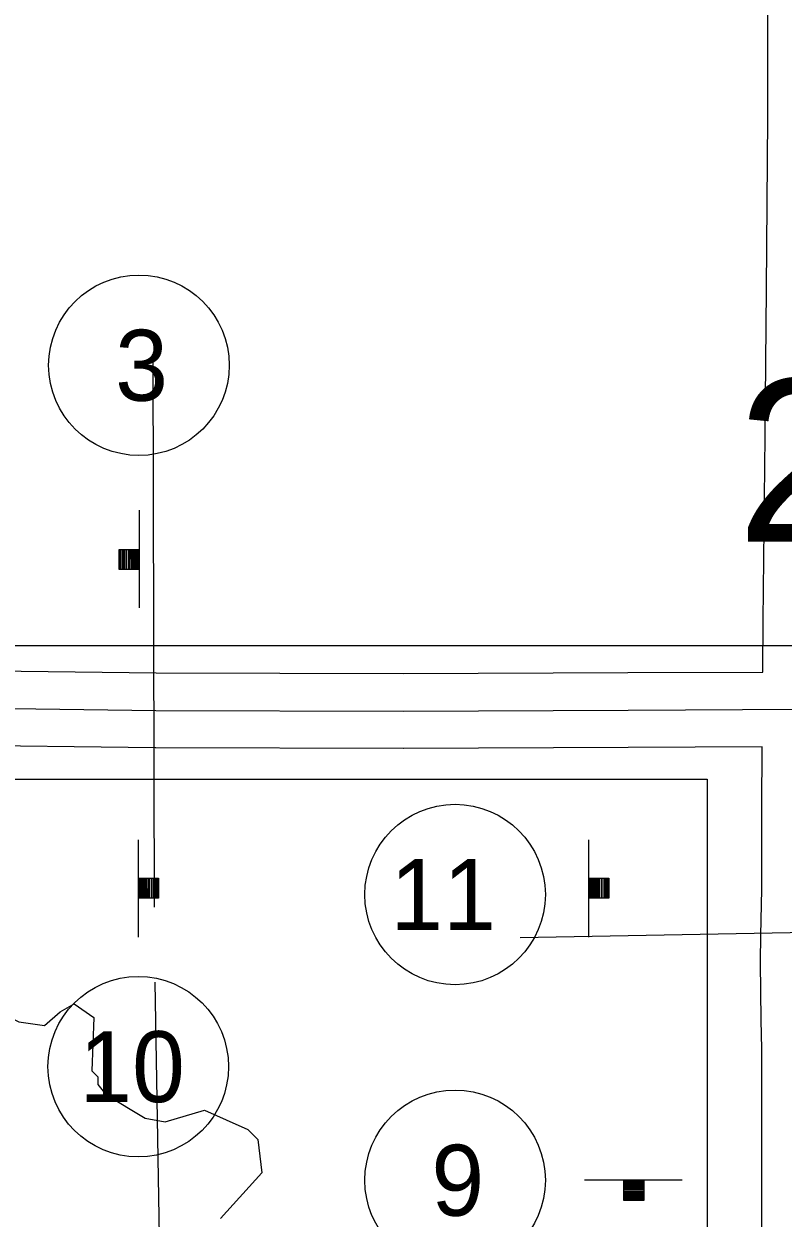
# Model space of a CAD drawing. Extents: x -2251611 to -2054719, y -2227156 to -2099355.
# Drawn here: x -2130609 to -2127401, y -2126976 to -2121927 of the extents above; entities that cross this region are included whole.
import ezdxf

# ---------------------------------------------------------------- set-up
doc = ezdxf.new("R2010")
doc.units = 0
for name, color, linetype in [('Default', 7, 'Continuous'), ('dsnTextFinalPlan', 7, 'Continuous'), ('dsnTextNote', 7, 'Continuous'), ('tdCoHydroRiver', 7, 'Continuous'), ('tdCoSecRteBand', 7, 'Continuous'), ('tdCoSectLinePart', 7, 'Continuous'), ('tdCoSectNmbr', 7, 'Continuous'), ('tdCoSurfAsphalt', 7, 'Continuous')]:
    doc.layers.add(name, color=color, linetype=linetype)

msp = doc.modelspace()

# ---------------------------------------------------------------- linework, layer by layer
at = {"layer": 'Default'}
for p, q in [((-2127105.2, -2124556.4), (-2138233.4, -2124556.4)), ((-2137523.9, -2125120.3), (-2127721.9, -2125120.3)), ((-2127721.9, -2125120.3), (-2127721.9, -2135863.1))]:
    msp.add_line(p, q, dxfattribs=at)
at = {"layer": 'dsnTextFinalPlan'}
for p, q in [((-2130120.8, -2124395.8), (-2130120.8, -2123983.3)), ((-2130200.7, -2124232.9), (-2130200.7, -2124149)), ((-2130195.9, -2124149), (-2130195.9, -2124232.9)), ((-2130192.5, -2124232.9), (-2130192.5, -2124149)), ((-2130187.7, -2124149), (-2130187.7, -2124232.9)), ((-2130184.4, -2124232.9), (-2130184.6, -2124149)), ((-2130178.2, -2124149), (-2130177.9, -2124232.9)), ((-2130174.8, -2124232.9), (-2130174.8, -2124149)), ((-2130168.3, -2124149), (-2130168.3, -2124232.9)), ((-2130162.7, -2124232.9), (-2130162.7, -2124149)), ((-2130157.9, -2124149), (-2130157.6, -2124232.9)), ((-2130154.5, -2124232.9), (-2130154.5, -2124149)), ((-2130150.6, -2124149), (-2130150.6, -2124232.9)), ((-2130145.5, -2124232.9), (-2130145.5, -2124149)), ((-2130142.4, -2124149), (-2130142.4, -2124232.9)), ((-2130139.1, -2124232.9), (-2130139.1, -2124149)), ((-2130135.1, -2124149), (-2130135.1, -2124232.9)), ((-2130131.2, -2124232.9), (-2130131.2, -2124149)), ((-2130127, -2124149), (-2130127, -2124232.9)), ((-2130126, -2125376.2), (-2130126, -2125788.7)), ((-2128222.6, -2125376.2), (-2128222.6, -2125788.7)), ((-2130119.8, -2125623), (-2130119.8, -2125539.1)), ((-2130115.5, -2125539.1), (-2130115.5, -2125623)), ((-2130111.6, -2125623), (-2130111.6, -2125539.1)), ((-2130107.7, -2125539.1), (-2130107.7, -2125623)), ((-2130104.3, -2125623), (-2130104.3, -2125539.1)), ((-2130101.2, -2125539.1), (-2130101.2, -2125623)), ((-2130096.1, -2125623), (-2130096.1, -2125539.1)), ((-2130092.2, -2125539.1), (-2130092.2, -2125623)), ((-2130088.8, -2125623), (-2130089.1, -2125539.1)), ((-2130084, -2125539.1), (-2130084, -2125623)), ((-2130078.4, -2125623), (-2130078.4, -2125539.1)), ((-2130071.9, -2125539.1), (-2130071.9, -2125623)), ((-2130068.6, -2125623), (-2130068.8, -2125539.1)), ((-2130062.4, -2125539.1), (-2130062.1, -2125623)), ((-2130059, -2125623), (-2130059, -2125539.1)), ((-2130054.2, -2125539.1), (-2130054.2, -2125623)), ((-2130050.8, -2125623), (-2130050.8, -2125539.1)), ((-2130046.1, -2125539.1), (-2130046.1, -2125623)), ((-2128216.4, -2125623), (-2128216.4, -2125539.1)), ((-2128212.1, -2125539.1), (-2128212.1, -2125623)), ((-2128208.2, -2125623), (-2128208.2, -2125539.1)), ((-2128204.3, -2125539.1), (-2128204.3, -2125623)), ((-2128200.9, -2125623), (-2128200.9, -2125539.1)), ((-2128197.8, -2125539.1), (-2128197.8, -2125623)), ((-2128192.7, -2125623), (-2128192.7, -2125539.1)), ((-2128188.8, -2125539.1), (-2128188.8, -2125623)), ((-2128185.4, -2125623), (-2128185.7, -2125539.1)), ((-2128180.6, -2125539.1), (-2128180.6, -2125623)), ((-2128175, -2125623), (-2128175, -2125539.1)), ((-2128168.5, -2125539.1), (-2128168.5, -2125623)), ((-2128165.2, -2125623), (-2128165.5, -2125539.1)), ((-2128159, -2125539.1), (-2128158.7, -2125623)), ((-2128155.6, -2125623), (-2128155.6, -2125539.1)), ((-2128150.8, -2125539.1), (-2128150.8, -2125623)), ((-2128147.5, -2125623), (-2128147.5, -2125539.1)), ((-2128142.7, -2125539.1), (-2128142.7, -2125623)), ((-2127827.3, -2126816.1), (-2128239.8, -2126816.1)), ((-2128074, -2126822.3), (-2127990.2, -2126822.3)), ((-2127990.2, -2126826.5), (-2128074, -2126826.5)), ((-2128074, -2126830.5), (-2127990.2, -2126830.5)), ((-2127990.2, -2126834.4), (-2128074, -2126834.4)), ((-2128074, -2126837.8), (-2127990.2, -2126837.8)), ((-2127990.2, -2126840.9), (-2128074, -2126840.9)), ((-2128074, -2126845.9), (-2127990.2, -2126845.9)), ((-2127990.2, -2126849.9), (-2128074, -2126849.9)), ((-2128074, -2126853.2), (-2127990.2, -2126853)), ((-2127990.2, -2126858), (-2128074, -2126858)), ((-2128074, -2126863.7), (-2127990.2, -2126863.7)), ((-2127990.2, -2126870.1), (-2128074, -2126870.1)), ((-2128074, -2126873.5), (-2127990.2, -2126873.2)), ((-2127990.2, -2126879.7), (-2128074, -2126880)), ((-2128074, -2126883.1), (-2127990.2, -2126883.1)), ((-2127990.2, -2126887.8), (-2128074, -2126887.8)), ((-2128074, -2126891.2), (-2127990.2, -2126891.2)), ((-2127990.2, -2126896), (-2128074, -2126896))]:
    msp.add_line(p, q, dxfattribs=at)
for points in [[(-2130122.2, -2124149), (-2130122.2, -2124233.4), (-2130206.6, -2124233.4), (-2130206.6, -2124149)], [(-2130124.5, -2125623), (-2130124.5, -2125538.6), (-2130040.2, -2125538.6), (-2130040.2, -2125623)], [(-2128221.1, -2125623), (-2128221.1, -2125538.6), (-2128136.8, -2125538.6), (-2128136.8, -2125623)], [(-2128074, -2126817.5), (-2127989.6, -2126817.5), (-2127989.6, -2126901.9), (-2128074, -2126901.9)]]:
    msp.add_lwpolyline(points, close=True, dxfattribs=at)
at = {"layer": 'dsnTextNote'}
for centre in [(-2130123, -2123370.5), (-2128786.9, -2125608.1), (-2130126, -2126335.9), (-2128786.9, -2126816.1)]:
    msp.add_circle(centre, 381.4, dxfattribs=at)
at = {"layer": 'tdCoHydroRiver'}
msp.add_lwpolyline([(-2131314.6, -2125681.1), (-2131214.6, -2125714.2), (-2131114.4, -2125813.9), (-2131014.3, -2125855.4), (-2130772.6, -2125863.1), (-2130722.5, -2125913), (-2130713.8, -2126071.3), (-2130663.7, -2126129.5), (-2130630.3, -2126146.1), (-2130522, -2126162.5), (-2130455.4, -2126104), (-2130397.2, -2126070.6), (-2130313.7, -2126128.7), (-2130321.5, -2126353.7), (-2130296.5, -2126378.6), (-2130296.4, -2126412), (-2130263, -2126453.5), (-2130096.1, -2126553.1), (-2130012.7, -2126569.6), (-2129846.2, -2126519.2), (-2129662.7, -2126602.1), (-2129620.9, -2126643.7), (-2129603.9, -2126785.3), (-2129778.4, -2126977.3)], dxfattribs=at)
at = {"layer": 'tdCoSecRteBand'}
for points in [[(-2132465.1, -2121321.7), (-2132476.8, -2121974.4), (-2132483.3, -2122587.6), (-2132483.3, -2123237.2), (-2132479.4, -2123808.3), (-2132479.4, -2123808.7), (-2132479.4, -2123809), (-2132478.1, -2124417.1), (-2132478.1, -2124417.3), (-2132478.1, -2124417.5), (-2132478.1, -2124633.3), (-2132478.1, -2124647.7), (-2132366.6, -2124647.7), (-2132201.4, -2124647.8), (-2132200.4, -2124647.8), (-2132199.5, -2124647.8), (-2131456.6, -2124656.9), (-2130964.9, -2124659.5), (-2130964.3, -2124659.5), (-2130963.7, -2124659.5), (-2130050.5, -2124671.2), (-2129005, -2124673.8)], [(-2129005, -2124673.8), (-2128056.3, -2124669.9), (-2127486.6, -2124667.4), (-2127484.6, -2124449.7), (-2127484.6, -2124449.7), (-2127484.6, -2124449.6), (-2127476.8, -2123671.1), (-2127471.6, -2123048.8), (-2127471.6, -2123048.7), (-2127471.6, -2123048.7), (-2127465.1, -2122324.1), (-2127465.1, -2121745.1)], [(-2127492.2, -2127472.7), (-2127491.1, -2126909.3), (-2127491.1, -2126260.9), (-2127492.9, -2126139.6), (-2127496.3, -2125894.8), (-2127496.4, -2125892.3), (-2127496.3, -2125889.9), (-2127494.5, -2125781), (-2127491.1, -2125585.2), (-2127491.1, -2125416), (-2127491.1, -2125176.4), (-2127491.1, -2125175.7), (-2127491.1, -2125175), (-2127490, -2125049.8), (-2127489.4, -2124984.2), (-2128054.9, -2124986.7), (-2128054.9, -2124986.7), (-2128055, -2124986.7), (-2129004.2, -2124990.6), (-2129004.7, -2124990.6), (-2129005.2, -2124990.6), (-2130052.1, -2124988), (-2130052.9, -2124988), (-2130053.7, -2124988), (-2130967.2, -2124976.3)]]:
    msp.add_lwpolyline(points, dxfattribs=at)
at = {"layer": 'tdCoSectLinePart'}
for points in [[(-2130064.9, -2123334.6), (-2130059.2, -2125661.6)], [(-2128512.6, -2125790.4), (-2124784.3, -2125720.6)], [(-2130056.1, -2125978.3), (-2129969.2, -2131020.9)]]:
    msp.add_lwpolyline(points, dxfattribs=at)
at = {"layer": 'tdCoSurfAsphalt'}
msp.add_lwpolyline([(-2132366.6, -2124806.1), (-2132201.4, -2124806.2), (-2131457.9, -2124815.3), (-2130965.8, -2124817.9), (-2130051.7, -2124829.6), (-2129004.8, -2124832.2), (-2128055.6, -2124828.3), (-2127329.6, -2124825.1)], dxfattribs=at)

# ---------------------------------------------------------------- texts
at = {"layer": 'dsnTextNote'}
for s, p in [('3', (-2130223.3, -2123520.5)), ('11', (-2129060.8, -2125758.1)), ('10', (-2130375, -2126485.9)), ('9', (-2128887.2, -2126966.1))]:
    msp.add_text(s, height=300, dxfattribs=at).set_placement(p)
at = {"layer": 'tdCoSectNmbr'}
msp.add_text('25', height=686.4, rotation=0.021, dxfattribs=at).set_placement((-2127594.8, -2124116.1))

doc.saveas('drawing.dxf')
